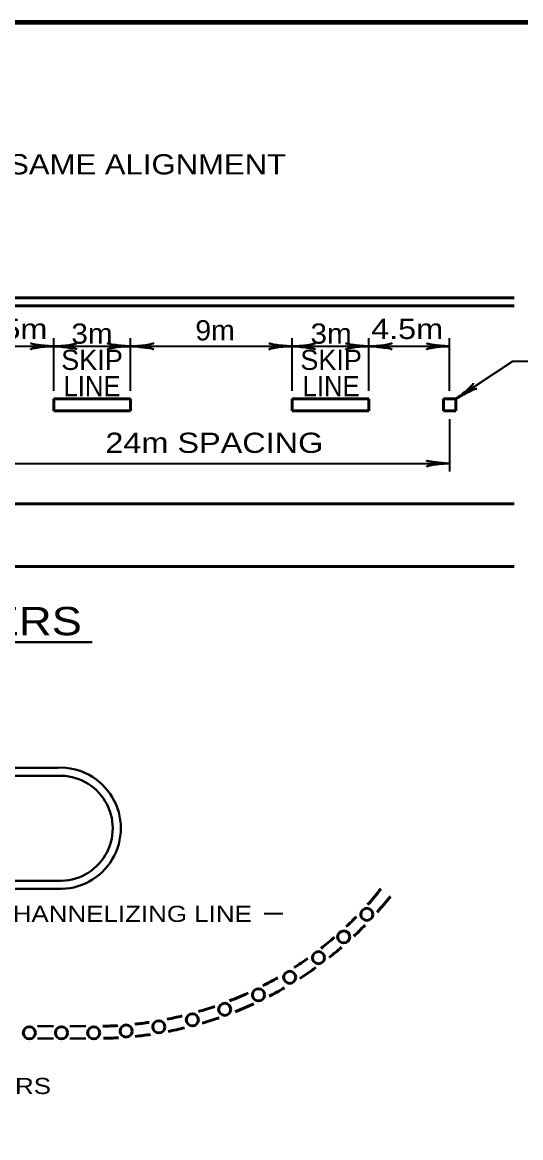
# Model space of a CAD drawing. Extents: x -96 to 617, y -65 to 388.
# Drawn here: x 422.4 to 484.1, y 245 to 383 of the extents above; entities that cross this region are included whole.
import ezdxf
from ezdxf.enums import TextEntityAlignment as Align

# ---------------------------------------------------------------- set-up
doc = ezdxf.new("R2010")
doc.units = 0
doc.layers.add('1', color=7, linetype='Continuous', lineweight=53)

msp = doc.modelspace()

# ---------------------------------------------------------------- linework, layer by layer
at = {"layer": '1'}
for p, q in [((323.265, 348.913), (483.265, 348.913)), ((323.265, 347.913), (483.265, 347.913)), ((426.265, 336.413), (426.265, 334.913)), ((426.265, 336.413), (435.765, 336.413)), ((435.765, 336.413), (435.765, 334.913)), ((455.765, 336.413), (455.765, 334.913)), ((455.765, 336.413), (465.265, 336.413)), ((465.265, 336.413), (465.265, 334.913)), ((474.515, 336.413), (474.515, 334.913)), ((474.515, 336.413), (476.015, 336.413)), ((476.015, 336.413), (476.015, 334.913)), ((426.265, 334.913), (435.765, 334.913)), ((455.765, 334.913), (465.265, 334.913)), ((474.515, 334.913), (476.015, 334.913)), ((323.265, 323.413), (483.265, 323.413)), ((323.265, 315.663), (483.265, 315.663))]:
    msp.add_line(p, q, dxfattribs=at)
at = {"layer": '1', "lineweight": 35}
for p, q in [((426.265, 337.413), (426.265, 343.913)), ((435.765, 337.413), (435.765, 343.913)), ((455.765, 337.413), (455.765, 343.913)), ((465.265, 337.413), (465.265, 343.913)), ((475.265, 337.413), (475.265, 343.913)), ((475.265, 333.913), (475.265, 327.413)), ((452.298, 272.738), (454.601, 272.738))]:
    msp.add_line(p, q, dxfattribs=at)
at = {"layer": '1', "lineweight": 40}
for p, q in [((375.796, 306.296), (431.03, 306.296)), ((335.757, 290.765), (426.757, 290.765)), ((335.757, 289.765), (426.757, 289.765)), ((335.757, 276.765), (426.757, 276.765)), ((335.757, 275.765), (426.757, 275.765)), ((424.257, 258.765), (426.257, 258.765)), ((428.257, 258.765), (430.257, 258.765)), ((424.257, 257.265), (426.257, 257.265)), ((428.257, 257.265), (430.257, 257.265))]:
    msp.add_line(p, q, dxfattribs=at)
at = {"layer": '1', "lineweight": 158}
msp.add_lwpolyline([(611.853, 383.009), (-47.897, 382.926), (-47.814, -55.407)], dxfattribs=at)
at = {"layer": '1', "lineweight": 35}
for points in [[(337.765, 342.913), (347.265, 342.913), (357.265, 342.913), (367.265, 342.913), (376.765, 342.913), (396.765, 342.913), (406.265, 342.913), (416.265, 342.913), (426.265, 342.913), (435.765, 342.913), (455.765, 342.913), (465.265, 342.913), (475.265, 342.913)], [(476.015, 336.413), (483.098, 341.057), (486.879, 341.057)], [(357.265, 328.413), (416.265, 328.413), (475.265, 328.413)]]:
    msp.add_lwpolyline(points, dxfattribs=at)
at = {"layer": '1'}
for centre in [(465.02, 272.611), (462.155, 269.819), (459.033, 267.247), (455.47, 264.822), (451.614, 262.655), (447.427, 260.854), (443.424, 259.568), (423.25, 257.955), (427.232, 257.955), (431.214, 257.955), (435.233, 258.172), (439.274, 258.687)]:
    msp.add_circle(centre, 0.75, dxfattribs=at)
at = {"layer": '1', "lineweight": 40}
for radius in [7.506, 6.506]:
    msp.add_arc((427.063, 283.265), radius, 267.66187, 92.33812, dxfattribs=at)
at = {"layer": '1'}
for radius, start, end in [(45.026, 318.26583, 321.50637), (46.526, 318.37606, 321.50637), (45.026, 313.43174, 315.6667), (46.526, 313.27436, 315.66937), (45.026, 308.20285, 310.95613), (46.526, 308.30603, 310.7662), (45.026, 302.97343, 305.56991), (46.526, 302.81375, 305.73396), (45.026, 297.25531, 299.94929), (45.026, 291.51971, 294.6909), (46.526, 297.40308, 300.04265), (45.026, 286.3144, 289.0298), (46.526, 291.67876, 294.78466), (45.026, 281.2699, 283.69101), (46.526, 286.39576, 289.0956), (45.026, 271.07812, 273.41876), (45.026, 276.11697, 278.36877), (46.526, 281.04124, 283.60692), (46.526, 271.14475, 273.40354), (46.526, 275.97343, 278.32873)]:
    msp.add_arc((431.516, 303.79), radius, start, end, dxfattribs=at)
at = {"layer": '1', "lineweight": 40}
for centre, major_axis, ratio, start_param, end_param in [((425.174, 342.637), (1.786, 0.156), 0.122415, 0.8963533, 3.1415927), ((425.174, 342.637), (1.786, 0.156), 0.122415, 0.8963533, 3.1415927), ((425.145, 343.125), (1.756, -0.176), 0.07063, 3.1407148, 5.41811), ((425.145, 343.125), (1.756, -0.176), 0.07063, 3.1407148, 5.41811), ((427.386, 342.702), (-1.756, 0.176), 0.07063, 3.1407148, 5.41811), ((427.386, 342.702), (-1.756, 0.176), 0.07063, 3.1407148, 5.41811), ((427.357, 343.19), (-1.786, -0.156), 0.122415, 0.8963533, 3.1415927), ((427.357, 343.19), (-1.786, -0.156), 0.122415, 0.8963533, 3.1415927), ((434.674, 342.637), (1.786, 0.156), 0.122415, 0.8963533, 3.1415927), ((434.674, 342.637), (1.786, 0.156), 0.122415, 0.8963533, 3.1415927), ((434.645, 343.125), (1.756, -0.176), 0.07063, 3.1407148, 5.41811), ((434.645, 343.125), (1.756, -0.176), 0.07063, 3.1407148, 5.41811), ((436.886, 342.702), (-1.756, 0.176), 0.07063, 3.1407148, 5.41811), ((436.857, 343.19), (-1.786, -0.156), 0.122415, 0.8963533, 3.1415927), ((454.674, 342.637), (1.786, 0.156), 0.122415, 0.8963533, 3.1415927), ((454.674, 342.637), (1.786, 0.156), 0.122415, 0.8963533, 3.1415927), ((454.674, 342.637), (1.786, 0.156), 0.122415, 0.8963533, 3.1415927), ((454.645, 343.125), (1.756, -0.176), 0.07063, 3.1407148, 5.41811), ((454.645, 343.125), (1.756, -0.176), 0.07063, 3.1407148, 5.41811), ((454.645, 343.125), (1.756, -0.176), 0.07063, 3.1407148, 5.41811), ((456.886, 342.702), (-1.756, 0.176), 0.07063, 3.1407148, 5.41811), ((456.886, 342.702), (-1.756, 0.176), 0.07063, 3.1407148, 5.41811), ((456.857, 343.19), (-1.786, -0.156), 0.122415, 0.8963533, 3.1415927), ((456.857, 343.19), (-1.786, -0.156), 0.122415, 0.8963533, 3.1415927), ((464.174, 342.637), (1.786, 0.156), 0.122415, 0.8963533, 3.1415927), ((464.174, 342.637), (1.786, 0.156), 0.122415, 0.8963533, 3.1415927), ((464.145, 343.125), (1.756, -0.176), 0.07063, 3.1407148, 5.41811), ((464.145, 343.125), (1.756, -0.176), 0.07063, 3.1407148, 5.41811), ((466.386, 342.702), (-1.756, 0.176), 0.07063, 3.1407148, 5.41811), ((466.386, 342.702), (-1.756, 0.176), 0.07063, 3.1407148, 5.41811), ((466.357, 343.19), (-1.786, -0.156), 0.122415, 0.8963533, 3.1415927), ((466.357, 343.19), (-1.786, -0.156), 0.122415, 0.8963533, 3.1415927), ((474.174, 342.637), (1.786, 0.156), 0.122415, 0.8963533, 3.1415927), ((474.174, 342.637), (1.786, 0.156), 0.122415, 0.8963533, 3.1415927), ((474.145, 343.125), (1.756, -0.176), 0.07063, 3.1407148, 5.41811), ((474.145, 343.125), (1.756, -0.176), 0.07063, 3.1407148, 5.41811), ((476.777, 337.243), (-1.408, -1.11), 0.122415, 0.8963533, 3.1415927), ((477.069, 336.851), (1.565, 0.816), 0.07063, 6.2823074, 8.5597026), ((474.145, 328.625), (1.756, -0.176), 0.07063, 3.1407148, 5.41811), ((474.145, 328.625), (1.756, -0.176), 0.07063, 3.1407148, 5.41811), ((474.174, 328.137), (1.786, 0.156), 0.122415, 0.8963533, 3.1415927), ((474.174, 328.137), (1.786, 0.156), 0.122415, 0.8963533, 3.1415927)]:
    msp.add_ellipse(centre, major_axis=major_axis, ratio=ratio, start_param=start_param, end_param=end_param, dxfattribs=at)

# ---------------------------------------------------------------- texts
at = {"layer": '1'}
for s, height, width, p in [('NOTE: INSTALL "P" MARKERS ON THE SAME ALIGNMENT', 2.5, 1.15, (349.111, 364.186)), ('TYPE C-4 WHITE MARKERS', 2, 1.2, (383.496, 250.376))]:
    msp.add_text(s, height=height, dxfattribs=dict(at, width=width)).set_placement(p)
for s, height, width, p in [('4.5m', 2.5, 1.2, (421.026, 343.813)), ('3m', 2.5, 1.1, (431.004, 343.238)), ('9m', 2.5, 1.05, (446.233, 343.646)), ('3m', 2.5, 1.1, (460.597, 343.238)), ('4.5m', 2.5, 1.2, (470.001, 343.813)), ('LINE', 2.5, 0.95, (431.004, 336.738)), ('LINE', 2.5, 0.95, (460.597, 336.738)), ('24m SPACING', 2.5, 1.2, (446.146, 329.723)), ('TYPE "P" MARKERS', 3.5, 1.2, (403.107, 307.157)), ('150mm TO 200mm SOLID WHITE CHANNELIZING LINE', 2, 1.2, (409.688, 271.675))]:
    msp.add_text(s, height=height, dxfattribs=dict(at, width=width)).set_placement(p, align=Align.CENTER)
for p in [(431.004, 339.988), (460.597, 339.988)]:
    msp.add_text('SKIP', height=2.5, dxfattribs=at).set_placement(p, align=Align.CENTER)

doc.saveas('drawing.dxf')
